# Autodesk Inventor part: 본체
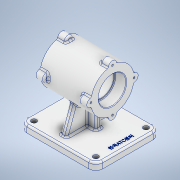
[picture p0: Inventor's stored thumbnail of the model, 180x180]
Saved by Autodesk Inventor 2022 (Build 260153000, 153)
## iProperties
Created: 2023-05
Part Number: 본체
Material: 알루미늄 6061
Document SubType Name: Modeling
Designer: Admin
Mass: 1215.39 g
Surface Area: 796.917 cm^2
Volume: 450.145 cm^3
Density: 2.7 g/cm^3
Appearance: 알루미늄 - 평지
Author: Admin
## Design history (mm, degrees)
sketch "스케치1"
  geometry: L1 (65, 55)-(-65, 55); L2 (-65, 55)-(-65, -55); L3 (-65, -55)-(65, -55); L4 (65, -55)-(65, 55); L5 (65, 55)-(-65, -55); L6 (-65, 55)-(65, -55); 1 further point
  constraints: 12 end point, 2 midpoint, 2 parallel, 1 horizontal, 1 perpendicular
  dimensions: "d0" = 130 distance of L2.end L3.end; "d1" = 110 distance of L1.end L2.end
extrude "돌출1" new body sketch "스케치1" distance "d2" = 12; taper "d3" = 0 deg
sketch "스케치2"
  geometry: L1 (-104.643, 82)-(101.082, 82); L2 (65, 0)-(-65, 0) reference; L3 (-48.5, 82)-(38.5, 82); L4 (38.5, 82)-(38.5, 119); L5 (38.5, 119)-(-48.5, 119); L6 (-48.5, 119)-(-48.5, 82); L7 (-5, -9.933)-(-5, 137.984); L8 (65, 0)-(65, 12) reference; 1 further point
  constraints: 12 end point, 2 horizontal, 2 parallel, 1 perpendicular, 1 point on line, 1 vertical, 1 other
  dimensions: "d4" = 82 distance between parallel lines of L2 L1; "d5" = 87 distance of L4.end L5.end; "d7" = 74 diameter of L5 L1; "d79" = 70 distance between parallel lines of L8 L7
revolve "회전1" sketch "스케치2" stored, may be unused: angle "d8" = 90 deg
sketch "스케치4"
  geometry: L1 (82, -59.548)-(82, 78.955); L2 (0, 55)-(0, -55) reference; L3 (12, 55)-(12, -55) reference; L4 (12, -41)-(82, -15.522); L5 (12, 41)-(82, 15.522); L6 (0, -55)-(12, -55) reference; L7 (0, 55)-(12, 55) reference; L8 (12, -41)-(12, 41); L9 (82, -15.522)-(82, 15.522); 1 further point
  constraints: 10 end point, 4 point on line, 2 collinear, 1 vertical
  dimensions: "d14" = 82 distance between parallel lines of L2 L1; "d15" = 14 distance from line of L6 L4.start; "d16" = 14 distance from line of L7 L5.start; "d17" = 110 deg angle of L3 L5; "d18" = 110 deg angle of L3 L4
extrude "돌출3" join sketch "스케치4" distance "d19" = 10; taper "d20" = 0 deg
sketch "스케치5"
  geometry: L1 (0, -107.2)-(0, 69.2) reference; C1 r 7 at (0, 37); 2 further points
  constraints: 1 centre point, 1 point on line, 1 vertical alignment, 1 other
  dimensions: "d21" = 14 diameter of C1
extrude "돌출4" join sketch "스케치5" distance "d22" = 14; taper "d23" = 0 deg
fillet "모깎기2" dims "d35" = 12
sketch "스케치8"
  geometry: L1 (65, -43)-(65, 43) reference; L2 (-53, -55)-(53, -55) reference; L3 (-65, 43)-(-65, -43) reference; L4 (53, 55)-(-53, 55) reference; A1 r 12 centre (53, 43) between (65, 43) and (53, 55) reference; A2 r 12 centre (53, -43) between (53, -55) and (65, -43) reference; A3 r 12 centre (-53, -43) between (-65, -43) and (-53, -55) reference; A4 r 12 centre (-53, 43) between (-53, 55) and (-65, 43) reference; 5 further points
  constraints: 4 coincident
hole "구멍2" sketch "스케치8" at (-53, 43), (-53, -43), (53, 43), (53, -43) diameter "d45" = 9; stored, may be unused: countersink angle "d49" = 90 deg, drill point angle "d51" = 118 deg; dims "d46" = 8, "d47" = 4, "d48" = 2, "d50" = 11.8
sketch "스케치12"
  geometry: L1 (-53, 12)-(53, 12) reference; L2 (-34.5, 45)-(38.5, 45) reference; L3 (15, 12)-(-25, 12); L4 (-5, 131.827)-(-5, -24.906); L5 (65, 0)-(65, 12) reference; L6 (51.242, 82)-(-55.922, 82); L7 (-48.5, 0)-(-57.5, 0) reference; L8 (15, 12)-(15, 82); L9 (-25, 12)-(-25, 82); L10 (15, 82)-(-25, 82); 1 further point
  constraints: 12 end point, 3 horizontal, 3 point on line, 2 perpendicular, 1 vertical, 1 other
  dimensions: "d60" = 70 distance between parallel lines of L5 L4; "d61" = 82 distance between parallel lines of L7 L6; "d62" = 40 distance between parallel lines of L8 L9
extrude "돌출5" join sketch "스케치12" stored distance "d63" = 10; taper "d64" = 0 deg
fillet "모깎기6" dims "d77" = 3
node "작업 평면4"
sketch "스케치16"
  geometry: L1 (47.085, 82)-(-74.554, 82); L2 (-48.5, 0)-(-57.5, 0) reference; L3 (38.5, 89)-(38.5, 75) reference; L4 (-48.5, 89)-(-48.5, 75) reference; L5 (38.5, 82)-(19.5, 82); L6 (19.5, 82)-(19.5, 105.5); L7 (19.5, 105.5)-(38.5, 105.5); L8 (38.5, 105.5)-(38.5, 82); L9 (19.5, 82)-(-29.5, 82); L10 (-29.5, 82)-(-29.5, 103); L11 (-29.5, 103)-(19.5, 103); L12 (19.5, 103)-(19.5, 82); L13 (-29.5, 82)-(-48.5, 82); L14 (-48.5, 82)-(-48.5, 105.5); L15 (-48.5, 105.5)-(-29.5, 105.5); L16 (-29.5, 105.5)-(-29.5, 82); 7 further points
  constraints: 26 end point, 6 parallel, 4 horizontal, 3 perpendicular, 1 midpoint, 1 point on line
  dimensions: "d82" = 82 distance between parallel lines of L2 L1; "d83" = 19 distance of L6.end L7.end; "d84" = 19 distance of L14.end L15.end; "d85" = 47 diameter of L7 L1; "d86" = 42 diameter of L11 L1; "d87" = 47 diameter of L15 L1
revolve "회전4" sketch "스케치16" stored, may be unused: angle "d88" = 90 deg
fillet "모깎기7" dims "d89" = 1
chamfer "모따기3" distance "d90" = 1; stored, may be unused: second distance "d91" = 2, angle "d92" = 45 deg
sketch "스케치17"
  geometry: L1 (37, -107.2)-(37, 69.2) reference; A1 r 37 centre (37, 0) between (43.969, 36.338) and (30.031, 36.338) reference; 2 further points
  constraints: 1 point on circle, 1 point on line
hole "구멍3" sketch "스케치17" at (37, 37) diameter "d93" = 3.242; stored, may be unused: countersink angle "d97" = 90 deg, drill point angle "d99" = 118 deg; dims "d94" = 8, "d95" = 4, "d96" = 2, "d98" = 10
fillet "모깎기8" dims "d103" = 3
fillet "모깎기9" dims "d107" = 3
sketch "스케치18"
  geometry: L1 (-5, -66.761)-(-5, 76.376); L2 (65, -43)-(65, 43) reference; 2 further points
  constraints: 2 end point, 1 horizontal alignment, 1 vertical, 1 other
  dimensions: "d108" = 70 distance between parallel lines of L2 L1; "d109" = 58 distance from line of L1 point (53, 0)
feature "엠보싱1" sketch "스케치18" dims "d0" = 130, "d1" = 110, "d110" = 0.5, "d111" = 0
node "솔리드1"
pattern_circular "원형 패턴1" dims angle "d25" = 360 deg
mirror "미러2"
mirror "미러3"
pattern_circular "원형 패턴2" dims angle "d101" = 360 deg
mirror "미러4"
pattern_circular "원형 패턴3" dims angle "d105" = 360 deg
mirror "미러5"
node "작업 평면1"
node "투영된 루프2"
feature "A9D066F2-1C7D-4E18-AEED-F7BC21143FA4" dims "d45" = 9, "d46" = 8, "d47" = 4, "d48" = 2, "d49" = 90 deg, "d50" = 11.8, "d51" = 118 deg
other parameters: "d81" = -5
